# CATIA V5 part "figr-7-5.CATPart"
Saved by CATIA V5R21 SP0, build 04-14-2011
Part number: Part1
Bounding box of the stored display mesh (mm): x -20 to 20, y -95 to 0, z 0 to 40
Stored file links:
  D:\CATIA V5R21 E-RESOURCES\CATIA-V5R21\catia-v5r21-prt\c07-catia-v5r20-prt\c07-catia-v5r21-figr-7-5.CATPart
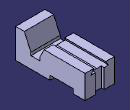
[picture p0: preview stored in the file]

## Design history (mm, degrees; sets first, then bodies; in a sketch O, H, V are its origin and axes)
Body1 (main body)
  Sketch1 on yz-plane, origin (0, 0, 0), H (0, 1, 0), V (0, 0, 1)
    line L1 (0, 0) -> (-16, 0)
    line L2 (-16, 0) -> (-16, 6)
    line L3 (-16, 6) -> (-48, 6)
    line L4 (-48, 6) -> (-48, 0)
    point P4 (-48, 0)
    line L5 (-48, 0) -> (-95, 0)
    line L6 (-95, 0) -> (-95, 40)
    line L7 (-95, 40) -> (-83, 40)
    line L8 (-83, 40) -> (-74, 20)
    line L9 (-74, 20) -> (-74, 16)
    line L10 (-74, 16) -> (-62, 16)
    line L11 (-62, 16) -> (-62, 20)
    line L12 (-62, 20) -> (-56, 32)
    line L13 (-56, 32) -> (0, 32)
    line L14 (0, 32) -> (0, 0)
    length L1 = 16
    length L3 = 32
    length L13 = 56
    distance L14 L6 = 95
    length L14 = 32
    length L6 = 40
    length L12 H = 6
    length L10 = 12
    length L7 = 12
    length L9 = 4
    length L2 = 6
    distance L10 L5 = 16
    length L12 V = 12
    horizontal: L1 H, L3 H, L5 H, L7 H, L10 H, L13 H
    vertical: L2 V, L4 V, L6 V, L9 V, L11 V, L14 V
    coincidence: P4 H
  Pad1: profile Sketch1, direction (1, 0, 0), length 20, mirrored extent
  Sketch2 on face of Pad1, origin (0, 0, 0), H (-1, 0, 0), V (0, 0, 1)
    axis line L1 (0, 0) -> (0, 40.9766)
    point P2 (0, 32)
    line L2 (0, 32) -> (-8, 32)
    point P3 (-8, 32)
    line L3 (-8, 32) -> (-12, 26)
    point P4 (-12, 26)
    line L4 (-12, 26) -> (0, 26)
    point P5 (0, 26)
    reference projected line E1 (-20, 32) -> (20, 32) from edge [face of Pad1 | face of Pad1]
    point P6 (0, 32)
    point P7 (8, 32)
    point P8 (12, 26)
    point P9 (0, 26)
    line L5 (0, 32) -> (8, 32)
    line L6 (8, 32) -> (12, 26)
    line L7 (12, 26) -> (0, 26)
    reference projected line E2 (-20, 0) -> (-20, 32) from edge [face of Pad1 | face of Pad1]
    reference projected line E3 (-20, 20) -> (-20, 40) from edge [face of Pad1 | face of Pad1]
    distance P4 E2 = 8
    length L3 V = 6
    distance P3 E3 = 12
    vertical: L1 V
    coincidence: P2 L1, P5 L1, L2 E1, P2 P6, P5 P9
    horizontal: L2 H, L4 H
    symmetry: P2 P6 L1, P3 P7 L1, P4 P8 L1, P5 P9 L1, L2 L5 L1, L3 L6 L1, L4 L7 L1
  Pocket1: profile Sketch2, direction (0, -1, 0), through (limit type 6)
  Sketch3 on face of Pad1, origin (0, 0, 0), H (-1, 0, 0), V (0, 0, 1)
    line L1 (-6, 0) -> (6, 0)
    line L2 (6, 0) -> (6, 26)
    line L3 (6, 26) -> (-6, 26)
    line L4 (-6, 26) -> (-6, 0)
    reference projected line E1 (-12, 26) -> (0, 26) from edge [face of Pad1 | face of Pocket1]
    length L1 = 12
    horizontal: L1 H, L3 H
    vertical: L2 V, L4 V
    midpoint: O L1
    coincidence: L3 E1
  Pocket2: profile Sketch3, direction (0, -1, 0), length 4
  Sketch4 "Sketch.4" on face of Pad1, origin (0, 0, 40), H (1, 0, 0), V (0, 1, 0)
    line L1 (-12.5, -95) -> (12.5, -95)
    line L2 (12.5, -95) -> (12.5, -92)
    line L3 (12.5, -92) -> (-12.5, -92)
    line L4 (-12.5, -92) -> (-12.5, -95)
    reference projected line E1 (-20, -95) -> (20, -95) from edge [face of Pad1 | face of Pad1]
    axis line L5 (0, 0) -> (0, -95)
    point P5 (0, -95)
    length L1 = 25
    length L2 = 3
    horizontal: L1 H, L3 H
    vertical: L2 V, L4 V, L5 V
    coincidence: L1 E1
    midpoint: P5 L1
